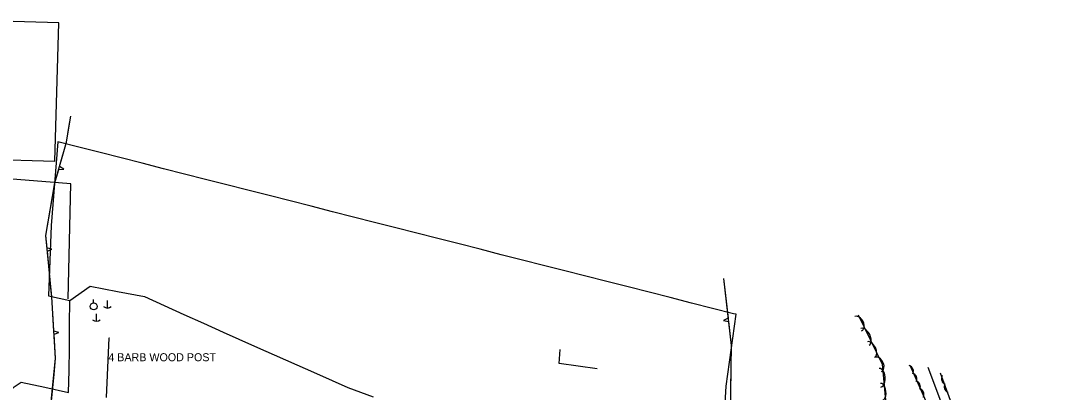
# Model space of a CAD drawing. Extents: x 954793 to 988390, y 1867850 to 1924428.
# Drawn here: x 963154 to 963802, y 1901087 to 1901319 of the extents above; entities that cross this region are included whole.
import ezdxf

# ---------------------------------------------------------------- set-up
doc = ezdxf.new("R2010")
doc.units = 0
for name, color, linetype in [('S_BUILDING', 7, 'Continuous'), ('S_FENCE', 7, 'Continuous'), ('S_MSC_PT_SYM', 7, 'Continuous'), ('S_OBSCURES', 7, 'Continuous'), ('S_PARKING', 7, 'Continuous'), ('S_SURVEY_TEXT_ANNOT', 7, 'Continuous'), ('S_TRAILS', 7, 'Continuous'), ('S_TREE', 7, 'Continuous'), ('S_UTILITY_POLE', 7, 'Continuous')]:
    doc.layers.add(name, color=color, linetype=linetype)

msp = doc.modelspace()

# ---------------------------------------------------------------- linework, layer by layer
at = {"layer": 'S_BUILDING'}
for p, q in [((963490.32, 1901105.41), (963490.97, 1901114.01)), ((963514.21, 1901102.05), (963490.32, 1901105.41))]:
    msp.add_line(p, q, dxfattribs=at)
msp.add_lwpolyline([(963134.91, 1901319.36), (963132.92, 1901250.76), (963130.72, 1901250.83), (963130.47, 1901242.31), (963133.26, 1901242.22), (963132.99, 1901232.86), (963175.46, 1901231.63), (963177.97, 1901318.11)], close=True, dxfattribs=at)
at = {"layer": 'S_FENCE'}
msp.add_lwpolyline([(963207.7, 1901084.13), (963209.46, 1901121.4)], dxfattribs=at)
at = {"layer": 'S_MSC_PT_SYM'}
for points in [[(963209.46, 1901121.4), (963209.46, 1901121.45), (963209.46, 1901121.4), (963209.41, 1901121.4), (963209.46, 1901121.4), (963209.46, 1901121.35), (963209.46, 1901121.4), (963209.51, 1901121.4)], [(963208.85, 1901111.73), (963208.85, 1901111.78), (963208.85, 1901111.73), (963208.8, 1901111.73), (963208.85, 1901111.73), (963208.85, 1901111.68), (963208.85, 1901111.73), (963208.9, 1901111.73)]]:
    msp.add_lwpolyline(points, dxfattribs=at)
at = {"layer": 'S_OBSCURES'}
msp.add_lwpolyline([(963593.37, 1901066.26), (963594.79, 1901091.22), (963597.91, 1901113.71), (963601.02, 1901136.2), (963599.38, 1901136.37), (963586.19, 1901139.72), (963573, 1901143.08), (963559.81, 1901146.44), (963546.62, 1901149.79), (963533.43, 1901153.15), (963520.24, 1901156.5), (963507.05, 1901159.86), (963493.86, 1901163.22), (963480.67, 1901166.57), (963467.48, 1901169.93), (963454.29, 1901173.28), (963441.1, 1901176.64), (963427.91, 1901180), (963414.71, 1901183.35), (963401.52, 1901186.71), (963388.33, 1901190.06), (963375.14, 1901193.42), (963361.95, 1901196.78), (963348.76, 1901200.13), (963335.57, 1901203.49), (963322.38, 1901206.84), (963309.19, 1901210.2), (963296, 1901213.55), (963282.81, 1901216.91), (963269.62, 1901220.27), (963256.43, 1901223.62), (963243.24, 1901226.98), (963230.05, 1901230.33), (963216.86, 1901233.69), (963203.67, 1901237.05), (963190.48, 1901240.4), (963177.29, 1901243.76), (963176.23, 1901230.72), (963175.18, 1901217.68), (963174.13, 1901204.64), (963173.08, 1901191.6), (963172.32, 1901169.63), (963171.56, 1901147.67), (963184.7, 1901144.6), (963197.46, 1901153.58), (963214.48, 1901150.35), (963231.51, 1901147.12), (963243.79, 1901141.55), (963256.07, 1901135.98), (963268.35, 1901130.42), (963280.63, 1901124.85), (963300.07, 1901116.24), (963319.51, 1901107.63), (963338.95, 1901099.01), (963358.39, 1901090.4), (963374.19, 1901084.53)], dxfattribs=at)
at = {"layer": 'S_PARKING'}
for points in [[(963183.75, 1901145.6), (963185.38, 1901217.5), (963141.19, 1901221.01)], [(963145.55, 1901056.85), (963144.8, 1901060.71), (963145.91, 1901083.11), (963149.45, 1901090.4), (963154.42, 1901093.65), (963169.18, 1901090.47), (963183.94, 1901087.3), (963184.29, 1901100.99), (963184.64, 1901114.68), (963184.67, 1901129.64), (963184.7, 1901144.6)]]:
    msp.add_lwpolyline(points, dxfattribs=at)
at = {"layer": 'S_TRAILS'}
msp.add_lwpolyline([(963720.68, 1901102.93), (963729.86, 1901078.57), (963737.12, 1901041.67), (963736.82, 1901010.17), (963736.19, 1900972.39), (963737.02, 1900932.99), (963733.56, 1900910.27)], dxfattribs=at)
at = {"layer": 'S_TREE'}
for p, q in [((963181.01, 1901226.58), (963178.41, 1901228.4)), ((963177.86, 1901226.51), (963181.01, 1901226.58)), ((963173.64, 1901176.64), (963170.56, 1901177.37)), ((963170.75, 1901175.41), (963173.64, 1901176.64)), ((963595.93, 1901133.55), (963593.06, 1901132.27)), ((963593.06, 1901132.27), (963596.16, 1901131.6)), ((963177.89, 1901124.75), (963174.83, 1901125.58)), ((963174.95, 1901123.62), (963177.89, 1901124.75))]:
    msp.add_line(p, q, dxfattribs=at)
for points in [[(963593.06, 1901158.38), (963597.9, 1901116.56), (963596.77, 1901047.88), (963596.62, 1900991.14), (963603.49, 1900936.15), (963574.91, 1900922.19), (963539.92, 1900933.03), (963505.81, 1900939.53), (963471.1, 1900947.23), (963427.36, 1900958.35), (963392.3, 1900970.25), (963356.69, 1900978.51), (963321.15, 1900992.3), (963283.58, 1900997.98), (963244.17, 1901010.8), (963207.46, 1901025.63), (963182.04, 1901038.21), (963172.79, 1901077.33), (963175.9, 1901108.5), (963173.49, 1901146.91), (963169.8, 1901185.3), (963175.44, 1901218.15), (963182.78, 1901243.46), (963185.42, 1901259.74)], [(963184.27, 1901252.66), (963185.42, 1901259.74)], [(963178.41, 1901228.4), (963182.78, 1901243.46), (963184.27, 1901252.66)], [(963172.68, 1901202.09), (963175.44, 1901218.15), (963177.86, 1901226.51)], [(963170.56, 1901177.37), (963169.8, 1901185.3), (963172.68, 1901202.09)], [(963173.14, 1901150.52), (963170.75, 1901175.41)], [(963593.06, 1901158.38), (963595.93, 1901133.55)], [(963174.83, 1901125.58), (963173.49, 1901146.91), (963173.14, 1901150.52)], [(963596.16, 1901131.6), (963597.9, 1901116.56), (963597.74, 1901106.7)], [(963677.14, 1901135.61), (963692.12, 1901104.97), (963694.73, 1901077.91), (963684.16, 1901051.93), (963644.28, 1901035.05), (963596.22, 1901011.78)], [(963174.92, 1901098.7), (963175.9, 1901108.5), (963174.95, 1901123.62)], [(963597.74, 1901106.7), (963597.33, 1901081.7)], [(963709.35, 1901104.18), (963726.11, 1901066.78), (963726.79, 1901001.15), (963710.37, 1900998.53), (963670.64, 1901009.52), (963633.44, 1901015.39), (963615.71, 1901025.28)], [(963172.83, 1901077.72), (963174.92, 1901098.7)], [(963881.16, 1901008.44), (963840.17, 1901021.34), (963817.52, 1901021.41), (963784.12, 1901020.02), (963746.89, 1901010.24), (963740.89, 1901043.18), (963734.8, 1901082.14), (963728.68, 1901099.22)]]:
    msp.add_lwpolyline(points, dxfattribs=at)
for centre, major_axis, ratio, start_param, end_param in [((963677.17, 1901130.13), (-2.16, 4.44), 0.688033, 3.143823, 6.285416), ((963681.46, 1901121.96), (-2.56, 5.25), 0.552266, 3.142949, 6.284542), ((963685.34, 1901114.03), (-2.34, 4.78), 0.542848, 3.142907, 6.284499), ((963689.61, 1901104.69), (-2.16, 4.44), 0.688033, 3.143823, 6.285416), ((963708.08, 1901100.52), (-1.33, 3.39), 0.998793, 3.872759, 5.64596), ((963690.82, 1901096.43), (-0.55, 5.83), 0.550945, 3.144019, 6.285612), ((963710.19, 1901095.62), (-1.33, 3.39), 0.998793, 3.872759, 5.64596), ((963732.79, 1901095.85), (1.23, -3.43), 0.999191, 3.825789, 5.598989), ((963691.67, 1901087.62), (-0.5, 5.31), 0.54155, 3.143943, 6.285536), ((963712.42, 1901090.83), (-1.33, 3.39), 0.998793, 3.872759, 5.64596), ((963734.52, 1901090.8), (1.23, -3.43), 0.999191, 3.825789, 5.598989), ((963714.62, 1901086.01), (-1.33, 3.39), 0.998793, 3.872759, 5.64596)]:
    msp.add_ellipse(centre, major_axis=major_axis, ratio=ratio, start_param=start_param, end_param=end_param, dxfattribs=at)
at = {"layer": 'S_UTILITY_POLE'}
for p, q in [((963199.56, 1901143.13), (963199.56, 1901145.24)), ((963208.2, 1901144.68), (963208.2, 1901139.95)), ((963201.32, 1901136.4), (963201.32, 1901131.67))]:
    msp.add_line(p, q, dxfattribs=at)
msp.add_circle((963199.68, 1901140.99), 2.13, dxfattribs=at)
for centre in [(963208.27, 1901143.38), (963201.38, 1901135.1)]:
    msp.add_arc(centre, 3.41, 226.39718, 313.60282, dxfattribs=at)

# ---------------------------------------------------------------- texts
at = {"layer": 'S_SURVEY_TEXT_ANNOT'}
msp.add_text('4 BARB WOOD POST', height=5, dxfattribs=at).set_placement((963208.85, 1901106.73))

doc.saveas('drawing.dxf')
